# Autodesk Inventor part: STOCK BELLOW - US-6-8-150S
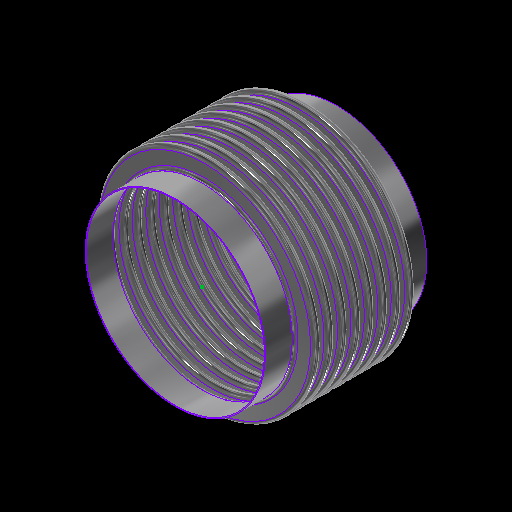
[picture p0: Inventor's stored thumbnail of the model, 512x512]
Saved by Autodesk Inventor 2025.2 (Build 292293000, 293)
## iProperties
Category: 20 GA (0.036 THICK)
RuleStatus: InUse
Created: 2024-01
Part Number: STOCK BELLOW - US-6-8-150S
Project: =STOCK BELLOWS: <Stock Number><SFILL>
Material: ASTM A240-304
Description: =STOCK BELLOWS: <Stock Number>, <SID_> I.D., <SOD_> O.D., <SPLY_> PLY, <Category>, <SNET_CONS> CONS.<PITCH_><STANGENT_> TANGENT<SFILL>
Document SubType Name: Sheet Metal
Designer: GS
Stock Number: U.S-6-8-150S
Surface Area: 4667.05 cm^2
Volume: 212.044 cm^3
Sheet Metal Rule: Default
Appearance: STAINLESS STEEL
Mass: 1708.5 g
Density: 8.05729 g/cm^3
THK: 0.036
ID: 3.500
OD: 4.250
CONS_: 2
PITCH: 0.500
TANGENT: 0.500
BELLOWS_UPSET: 0.000
d79: 1.000
d82: 1.000
d83: 26.000
d84: 24.000
d174: 8
d214: 8
STHK_: 0.036
SID_: 6.625
SOD_: 8.125
SPITCH_: 0.500
STANGENT__: 1.000
SBELLOWS_UPSET_: 0.000
SDIFF_TAN: 1.000
d252: 2
d275: 2
d287: 0.050
d289: 0.500
d290: 0.000
SOD_NECK: 6 11/16
PLY: 1
PSET: 4.178
PBAR: 1.035
COUNTER: 1.500
NET_TUBE: 3.071
CONS: 2
S_CONS: 0
NET_CONS: 2
ID_M: 88.90 mm
OD_M: 107.95 mm
THK_M: 0.91 mm
ID_U: 3.500 in
OD_U: 4.250 in
THK_U: 0.036 in
TANGENT2: 0.500
TAN_TO_TAN: 1.000 in
d80: 2.571
d81: 10
SID: 2.375
SCONS_: 8
SPITCH: 0.250
STANGENT_: 1.000
SBELLOWS_UPSET: 0.000
SNET_CONS: 8
SS_CONS: 0
SCONS: 8
d190: 8
d191: 1
d192: 1
d193: 8
d194: 0
SIZE: 6.00
PRESSURE: 150
d230: 8
STANGENT: 4.000
SPLY_: 1
d233: 8
d234: 0
d263: 2
d265: 1
d268: 2
d269: 0
d286: 2
d288: 1
d291: 2
d292: 0
SREROLL: 0.750
BLETP: 0.000 ul
PRES_Copy: 85
MATTABLE: 20 GA (0.036 THICK)
PART_NUMBER: U.S-6-8-150S
PITCH_: =, <SPITCH_> PITCH,
CFILL: .
SFILL: .
MESH: ,
COMP: 0.83
EXT: 0.42
LAT: 0.15
ANG: 573
ASR: 1823
LSR: 8364
ANSR: 195
PRES: 150
COMPM: 8.3
EXTM: 4.15
LATM: 1.50
ASRM: 319.262
PRESM: 10.342
LSRM: 1464.787
ANSRM: 34.15
TEMPMIN: 20
TEMPMAX: 800
TEMPMINM: -7
TEMPMAXM: 427
WEIGHTM: 1.709
WEIGHT: 3.767
Author: GS
Keywords: 20 GA (0.036 THICK)
Comments: =STOCK BELLOW - <STOCK NUMBER>
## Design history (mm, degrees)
sketch "Sketch2"
  geometry: L1 (0, -177.245)-(0, 562.856) reference; L2 (45.364, 0)-(44.45, 0); L3 (48.082, -2.718)-(50.343, -2.718); L4 (48.082, -3.632)-(50.343, -3.632); L5 (50.343, -9.982)-(48.082, -9.982); L6 (50.343, -9.068)-(48.082, -9.068); L7 (45.364, -12.7)-(44.45, -12.7); L8 (48.082, 0)-(48.082, -12.7); L9 (50.343, -6.35)-(53.975, -6.35); L10 (44.45, 0)-(44.45, -12.7); L11 (20.376, 102.841)-(20.376, 101.926); L12 (58.262, 457.127)-(58.262, 349.177); L13 (58.262, 444.427)-(58.262, 336.477); L14 (93.133, -58.817)-(93.133, -71.517); L15 (118.746, -66.401)-(118.746, -66.401); L16 (50.343, -9.068)-(50.343, -9.982); L17 (48.082, -9.068)-(48.082, -9.982); L18 (48.082, -9.525)-(50.343, -9.525); L19 (53.975, 0)-(53.975, -12.7); L20 (-50.343, -9.068)-(-50.343, -9.982); L21 (-50.343, -2.718)-(-48.082, -2.718); L22 (-50.343, -3.632)-(-48.082, -3.632); L23 (-48.082, -9.068)-(-50.343, -9.068); L24 (-50.343, -9.525)-(-48.082, -9.525); L25 (-48.082, -9.982)-(-50.343, -9.982); L26 (-48.082, -9.068)-(-48.082, -9.982); L27 (-44.45, 0.653)-(-44.45, -12.047); L28 (-48.082, -6.35)-(-44.45, -6.35); L29 (-50.343, 0.653)-(-50.343, -12.7); L30 (-53.061, 0)-(-53.975, 0); L31 (-53.975, 0)-(-53.975, -12.7); L32 (-53.061, -12.7)-(-53.975, -12.7); A1 r 2.718 centre (48.082, 0) between (45.364, 0) and (48.082, -2.718); A2 r 3.632 centre (48.082, 0) between (44.45, 0) and (48.082, -3.632); A3 r 3.632 centre (50.343, -6.35) between (50.343, -9.982) and (50.343, -2.718); A4 r 2.718 centre (50.343, -6.35) between (50.343, -9.068) and (50.343, -3.632); A5 r 2.718 centre (48.082, -12.7) between (48.082, -9.982) and (45.364, -12.7); A6 r 3.632 centre (48.082, -12.7) between (48.082, -9.068) and (44.45, -12.7); A7 r 3.175 centre (50.343, -6.35) between (50.343, -9.525) and (53.518, -6.35); A8 r 3.175 centre (48.082, -12.7) between (48.082, -9.525) and (44.907, -12.7); A9 r 2.718 centre (-50.343, -12.7) between (-50.343, -9.982) and (-53.061, -12.7); A10 r 2.718 centre (-48.082, -6.35) between (-48.082, -9.068) and (-48.082, -3.632); A11 r 3.175 centre (-48.082, -6.35) between (-48.082, -9.525) and (-44.907, -6.35); A12 r 3.632 centre (-48.082, -6.35) between (-48.082, -9.982) and (-48.082, -2.718); A13 r 3.175 centre (-50.343, -12.7) between (-50.343, -9.525) and (-53.518, -12.7); A14 r 3.632 centre (-50.343, -12.7) between (-50.343, -9.068) and (-53.975, -12.7); A15 r 2.718 centre (-50.343, 0) between (-53.061, 0) and (-50.343, -2.718); A16 r 3.632 centre (-50.343, 0) between (-53.975, 0) and (-50.343, -3.632); 10 further points
  constraints: 62 end point, 38 point on circle, 20 tangent, 16 centre point, 12 parallel, 9 midpoint, 7 vertical, 6 coincident, 6 concentric, 6 point on line, 4 equal radius, 4 perpendicular, 3 horizontal, 1 collinear, 1 horizontal alignment, 10 other
  dimensions: "THK" = 0.9144 distance of L11.start L11.end; "ID" = 88.9 distance of L11.end point (20.376, 13.026); "OD" = 107.95 distance of L12.start L12.end; "PITCH" = 12.7 distance of L12.start L13.start; "TANGENT" = 12.7 distance of L14.start L14.end; "BELLOWS_UPSET" = 0 distance of L15.start L15.end; "d43" = 88.9 diameter of L10 L1 (= ID); "d44" = 107.95 diameter of L9.end L1 (= OD); "d45" = 0.9144 distance between parallel lines of L5 L6 (computed from THK, PLY); "d46" = 3.6322 radius of A3 (computed from PITCH, THK, PLY); "UPSET_PITCH" = 12.7 distance of L2.end L7.end (derived); "SIDEWALL_ANGLE" = 360 deg dimension on L3 L9 (derived); "CON_GAP" = 5.4356 distance of point (48.082, -9.068) point (48.082, -3.632) (derived); "TAN1" = 4.98728 dimension on A8 (derived); "TAN2" = 4.98728 dimension on A7 (derived); "LEG1" = 2.2606 distance of L18.start L18.end (derived); "d278" = 0.9144 distance between parallel lines of L25 L23 (derived); "d279" = 3.6322 radius of A12 (derived); "d280" = 12.7 distance of L30.end L31.end (derived); "d281" = 360 deg dimension on L21 L28 (derived); "d282" = 5.4356 distance of point (-50.343, -9.068) point (-50.343, -3.632) (derived); "d283" = 4.98728 dimension on A13 (derived); "d284" = 4.98728 dimension on A11 (derived); "d285" = 2.2606 distance of L24.start L24.end (derived); "d293" = 88.9 diameter of L27 L1 (derived); "d294" = 107.95 diameter of L31 L1 (derived)
  node "Sketch Rectangular Pattern1" dims "d31" = 25.4, "ID" = 88.9
  node "Sketch Rectangular Pattern2" dims "d39" = 25.4, "PITCH" = 12.7
revolve "CONS" stored, may be unused: angle "d48" = 90 deg
node "BELLOW MIDPLANE"
pattern_linear "Rectangular Pattern2" dims "d52" = 12.7 (= UPSET_PITCH)
sketch "Sketch5"
  geometry: C1 r 45.364 at (0, 0) reference; C2 r 44.45 at (0, 0) reference
extrude "TANGENT" new body sketch "Sketch5" distance "d53" = 12.7 (= TANGENT); taper "d54" = 0 deg
revolve "SAMETAN" stored, may be unused: angle "d65" = 90 deg
revolve "DIFFTAN" stored, may be unused: angle "d70" = 90 deg
sketch "Sketch9"
  geometry: L1 (53.319, 0)-(-53.319, 0) reference; L2 (0, -17.78)-(0, 17.78) reference; L3 (38.085, 0)-(-38.085, 0); L4 (38.085, -11.906)-(38.085, 11.906); L5 (25.385, -11.906)-(25.385, 11.906); L6 (13.15, 11.906)-(13.15, -11.906); L7 (-25.385, -11.906)-(-25.385, 11.906); L8 (-38.085, -11.906)-(-38.085, 11.906); L9 (37.291, -11.906)-(37.291, 11.906); L10 (38.085, -11.906)-(37.291, -11.906); L11 (38.085, 11.906)-(37.291, 11.906); L12 (13.546, 11.906)-(12.753, 11.906); L13 (12.753, 11.906)-(12.753, -11.906); L14 (12.753, -11.906)-(13.546, -11.906); L15 (13.546, -11.906)-(13.546, 11.906); L16 (-13.546, 11.906)-(-13.546, -11.906); L17 (-13.15, 11.906)-(-13.15, -11.906); L18 (-13.546, -11.906)-(-12.753, -11.906); L19 (-12.753, -11.906)-(-12.753, 11.906); L20 (-12.753, 11.906)-(-13.546, 11.906); L21 (-38.085, -11.906)-(-37.291, -11.906); L22 (-37.291, -11.906)-(-37.291, 11.906); L23 (-37.291, 11.906)-(-38.085, 11.906); L24 (-38.085, 11.906)-(-38.085, -11.906); L25 (38.085, -0.397)-(-38.085, -0.397); L26 (-38.085, -0.397)-(-38.085, 0.397); L27 (-38.085, 0.397)-(38.085, 0.397); L28 (38.085, 0.397)-(38.085, -0.397); L29 (-38.085, 11.906)-(38.085, 11.906); L30 (38.085, 11.906)-(38.085, 12.7); L31 (38.085, 12.7)-(-38.085, 12.7); L32 (-38.085, 12.7)-(-38.085, 11.906); L33 (38.085, -11.906)-(-38.085, -11.906); L34 (-38.085, -11.906)-(-38.085, -12.7); L35 (-38.085, -12.7)-(38.085, -12.7); L36 (38.085, -12.7)-(38.085, -11.906); 30 further points
  constraints: 68 end point, 13 midpoint, 13 parallel, 8 horizontal, 7 perpendicular, 6 equal length, 3 point on line, 2 vertical, 14 other
  dimensions: "d115" = 23.8125 distance of L4.start L4.end (derived); "d116" = 12.7 distance between parallel lines of L4 L5 (derived); "d117" = 12.23516 distance between parallel lines of L5 L6 (derived); "d125" = 38.53427 distance between parallel lines of L7 L6 (derived); "d127" = 12.7 distance between parallel lines of L8 L7 (derived); "d128" = 24.93516 distance between parallel lines of L6 L4 (derived); "d130" = 76.16943 distance between parallel lines of L8 L4 (derived); "RULER_THK" = 0.79375 distance between parallel lines of L4 L9; "d135" = 0.79375 distance of L13.end L14.end (derived); "d138" = 26.29911 distance of L13.end L16.end (derived); "d143" = 0.79375 distance of L22.end L8.end (derived); "d144" = 0.79375 distance between parallel lines of L27 L25 (derived)
extrude "RULER" join sketch "Sketch9" distance "d149" = 0.79375 (derived); taper "d150" = 0 deg
extrude "BARS" join sketch "Sketch9" distance "d151" = 0.79375 (derived); taper "d152" = 0 deg
pattern_linear "Rectangular Pattern4" dims "d155" = 26.29911 (derived)
sketch "Sketch13"
  geometry: L1 (93.149, -52.467)-(93.149, -77.867); L2 (85.052, 0)-(84.138, 0); L3 (85.052, -12.7)-(84.138, -12.7); L4 (99.555, -9.982)-(87.77, -9.982); L5 (99.555, -9.068)-(87.77, -9.068); L6 (99.555, -6.35)-(103.188, -6.35); L7 (87.77, -2.718)-(99.555, -2.718); L8 (87.77, 0)-(87.77, -12.7); L9 (84.138, 0)-(84.138, -12.7); L10 (58.254, -290.056)-(58.254, -496.431); L11 (58.254, -302.756)-(58.254, -509.131); L12 (58.254, -328.156)-(58.254, -534.531); L13 (58.254, -340.856)-(58.254, -547.231); L14 (58.254, -353.556)-(58.254, -559.931); L15 (58.254, -366.256)-(58.254, -572.631); L16 (58.254, -378.956)-(58.254, -585.331); L17 (58.254, -315.456)-(58.254, -521.831); L18 (20.376, 102.841)-(20.376, 101.926); L19 (87.77, -3.632)-(99.555, -3.632); L20 (0, -722.965)-(0, 240.475) reference; L21 (-23.752, 0)-(142.514, 0) reference; A1 r 2.718 centre (87.77, 0) between (85.052, 0) and (87.77, -2.718); A2 r 2.718 centre (87.77, -12.7) between (87.77, -9.982) and (85.052, -12.7); A3 r 3.632 centre (87.77, -12.7) between (87.77, -9.068) and (84.138, -12.7); A4 r 2.718 centre (99.555, -6.35) between (99.555, -9.068) and (99.555, -3.632); A5 r 3.632 centre (99.555, -6.35) between (99.555, -9.982) and (99.555, -2.718); A6 r 3.632 centre (87.77, 0) between (84.138, 0) and (87.77, -3.632); 6 further points; 1 other entity
  constraints: 38 end point, 15 point on circle, 9 tangent, 6 centre point, 6 parallel, 5 vertical alignment, 4 point on line, 4 vertical, 3 coincident, 3 concentric, 2 collinear, 2 equal radius, 1 horizontal, 1 perpendicular, 23 other
  dimensions: "SBELLOWS_UPSET_" = 0 distance of point (118.762, -66.401) point (118.762, -66.401); "STOTAL_THK_BELLOW__" = 0.9144 distance between parallel lines of L4 L5 (derived); "d224" = 3.6322 radius of A5 (derived); "d225" = 12.7 distance of L2.end L3.end (derived); "SSIDEWALL_ANGLE_" = 0 deg angle of L7 L6 (derived); "SSCON_GAP_" = 5.4356 distance of point (87.77, -9.068) point (87.77, -3.632) (derived); "d235" = 168.275 diameter of L9 L20 (derived); "d236" = 206.375 diameter of L6.end L20 (derived)
  node "Sketch Rectangular Pattern4" dims "d228" = 25.4
  node "Sketch Rectangular Pattern5" dims "d229" = 25.4
revolve "SBELLOW" stored, may be unused: angle "d197" = 90 deg
pattern_linear "Rectangular Pattern5" dims "d204" = 12.7 (derived)
revolve "STANGENT" stored, may be unused: angle "d240" = 90 deg
revolve "SSAMETAN" stored, may be unused: angle "d241" = 90 deg
revolve "SDIFFTAN" stored, may be unused: angle "d246" = 90 deg
revolve "INVCON" stored, may be unused: angle "d295" = 90 deg
pattern_linear "Rectangular Pattern6" dims "d298" = 12.7 (derived)
revolve "INVTANGENT" stored, may be unused: angle "d302" = 90 deg
revolve "INVSAMETAN" stored, may be unused: angle "d307" = 90 deg
revolve "INVDIFFTAN" stored, may be unused: angle "d312" = 90 deg
sketch "ID BELLOW MOUNT CALC"
  geometry: L1 (44.45, 0)-(38.1, 0); L2 (38.1, 0)-(38.1, 12.7); L3 (38.1, 12.7)-(44.45, 12.7); L4 (44.45, 12.7)-(44.45, 0); L5 (36.513, 12.7)-(35.598, 12.7); L6 (35.598, 12.7)-(35.598, 0); L7 (35.598, 0)-(36.513, 0); L8 (36.513, 0)-(36.513, 12.7); L9 (0, -2.54)-(0, 15.24) reference; L10 (-8.89, 0)-(53.34, 0) reference; 1 further point
  constraints: 16 end point, 5 parallel, 2 collinear, 2 horizontal, 2 perpendicular
  dimensions: "d314" = 12.7 distance of L5.end L6.end (derived); "d315" = 0.9144 distance of L5.start L5.end (derived); "IG" = 1.5875 distance between parallel lines of L2 L8; "PIPE_OD" = 88.9 diameter of L4 L9; "PIPE_WALL" = 6.35 distance of L2.end L3.end; "ID_MT_BELLOW" = 71.1962 diameter of L6 L9 (derived)
revolve "CFILL" stored, may be unused: angle "d320" = 90 deg
pattern_linear "Rectangular Pattern7" dims "d323" = 12.7 (derived)
revolve "SFILL" stored, may be unused: angle "d324" = 90 deg
pattern_linear "Rectangular Pattern8" dims "d327" = 12.7 (derived)
node "STOCK BELLOW MIDPLANE"
node "BELLOW"
sketch "Sketch6"
  geometry: L1 (-12.7, 45.364)-(0, 45.364); L2 (0, 45.364)-(0, 44.45); L3 (0, 44.45)-(-12.7, 44.45); L4 (-12.7, 44.45)-(-12.7, 45.364); L5 (10.16, 0)-(-60.96, 0) reference; L6 (-38.1, -89.422)-(-38.1, 153.44) reference; 1 further point
  constraints: 8 end point, 2 parallel, 1 horizontal, 1 perpendicular
  dimensions: "d61" = 12.7 distance of L2.end L3.end (derived); "d62" = 0.9144 distance of L1.end L2.end (derived); "d63" = 88.9 diameter of L3 L5 (derived); "d64" = 25.4 distance between parallel lines of L4 L6 (derived)
sketch "Sketch12"
  geometry: 1 further point
sketch "Sketch14"
  geometry: L1 (-25.4, 85.052)-(0, 85.052); L2 (0, 85.052)-(0, 84.138); L3 (0, 84.138)-(-25.4, 84.138); L4 (-25.4, 84.138)-(-25.4, 85.052); L5 (5.08, 0)-(-30.48, 0) reference; L6 (0, -17.01)-(0, 102.062) reference; 1 further point
  constraints: 8 end point, 2 parallel, 1 collinear, 1 horizontal, 1 perpendicular
  dimensions: "d237" = 0.9144 distance of L3.end L1.start (derived); "d238" = 168.275 diameter of L3 L5 (derived); "d239" = 25.4 distance of L1.start L1.end (derived); "SOD_NECK" = 170.1038 diameter of L1 L5 (derived)
sketch "Sketch15"
  geometry: L1 (-17.01, 0)-(102.062, 0) reference; L2 (84.138, -101.6)-(85.052, -101.6); L3 (85.052, -101.6)-(85.052, -127); L4 (85.052, -127)-(84.138, -127); L5 (84.138, -127)-(84.138, -101.6); L6 (0, -154.94)-(0, 40.64) reference; 1 further point
  constraints: 8 end point, 2 parallel, 1 horizontal, 1 perpendicular
  dimensions: "d205" = 25.4 distance of L4.end L2.start (derived); "d206" = 0.9144 distance of L3.end L4.end (derived); "d207" = 168.275 diameter of L5 L6 (derived); "d208" = 101.6 distance between parallel lines of L1 L2 (derived)
node "TANGENT_"
node "SAME_TAN"
sketch "Sketch8"
  geometry: L1 (45.364, -25.4)-(44.45, -25.4); L2 (44.45, -25.4)-(44.45, -38.1); L3 (44.45, -38.1)-(45.364, -38.1); L4 (45.364, -38.1)-(45.364, -25.4); L5 (0, -48.26)-(0, 22.86) reference; L6 (-89.422, 0)-(153.44, 0) reference; 1 further point
  constraints: 8 end point, 2 parallel, 1 horizontal, 1 perpendicular
  dimensions: "d66" = 88.9 diameter of L2 L5 (derived); "TOTAL_THK_BELLOW" = 0.9144 distance of L2.end L3.end (derived); "d68" = 25.4 distance between parallel lines of L1 L6 (derived); "d69" = 12.7 distance of L1.end L2.end (derived)
node "DIFF_TAN"
node "Sketch Rectangular Pattern3" dims "d138" = 26.29911 (derived), "d141" = 25.4
node "SBELLOW_"
node "STANGENT_"
node "SSAME_TAN"
sketch "Sketch16"
  geometry: L1 (85.052, -101.6)-(84.138, -101.6); L2 (84.138, -101.6)-(84.138, -127); L3 (84.138, -127)-(85.052, -127); L4 (85.052, -127)-(85.052, -101.6); L5 (0, -154.94)-(0, 40.64) reference; L6 (-17.01, 0)-(102.062, 0) reference; 1 further point
  constraints: 8 end point, 2 parallel, 1 horizontal, 1 perpendicular
  dimensions: "SDIFF_TAN" = 25.4 distance of L3.end L1.start; "d243" = 0.9144 distance of L2.end L3.end (derived); "d244" = 101.6 distance between parallel lines of L1 L6 (derived); "d245" = 168.275 diameter of L2 L5 (derived)
node "SDIFF_TAN"
body "Solid15"
sketch "Sketch17"
  geometry: L1 (53.975, 12.7)-(53.061, 12.7); L2 (53.061, 12.7)-(53.061, 0); L3 (53.061, 0)-(53.975, 0); L4 (53.975, 0)-(53.975, 12.7); L5 (0, -2.54)-(0, 15.24) reference; L6 (-10.795, 0)-(64.77, 0) reference; 2 further points
  constraints: 8 end point, 2 parallel, 1 horizontal, 1 midpoint, 1 perpendicular, 1 point on line
  dimensions: "INVTANGENT" = 12.7 distance of L3.end L1.start (derived); "d300" = 0.9144 distance of L1.start L1.end (derived); "d301" = 107.95 diameter of L4 L5 (derived)
body "Solid16"
sketch "Sketch18"
  geometry: L1 (53.975, -25.4)-(53.061, -25.4); L2 (53.061, -25.4)-(53.061, -38.1); L3 (53.061, -38.1)-(53.975, -38.1); L4 (53.975, -38.1)-(53.975, -25.4); L5 (-10.795, 0)-(64.77, 0) reference; L6 (0, -48.26)-(0, 22.86) reference; 1 further point
  constraints: 8 end point, 2 parallel, 1 horizontal, 1 perpendicular
  dimensions: "d303" = 25.4 distance between parallel lines of L1 L5 (derived); "d304" = 12.7 distance of L3.end L1.start (derived); "d305" = 0.9144 distance of L2.end L3.end (derived); "d306" = 107.95 diameter of L4 L6 (derived)
body "Solid17"
sketch "Sketch19"
  geometry: L1 (53.975, -25.4)-(53.061, -25.4); L2 (53.061, -25.4)-(53.061, -38.1); L3 (53.061, -38.1)-(53.975, -38.1); L4 (53.975, -38.1)-(53.975, -25.4); L5 (0, -48.26)-(0, 22.86) reference; L6 (-10.795, 0)-(64.77, 0) reference; 1 further point
  constraints: 8 end point, 2 parallel, 1 horizontal, 1 perpendicular
  dimensions: "d308" = 12.7 distance of L1.end L2.end (derived); "d309" = 107.95 diameter of L4 L5 (derived); "d310" = 0.9144 distance of L2.end L3.end (derived); "d311" = 25.4 distance between parallel lines of L1 L6 (derived)
body "Solid18"
body "Solid19"
body "Solid20"
other parameters: "BMPL" = -50.8, "PSET" = 106.1212 (computed from OD, THK, PLY) [user parameter], "PBAR" = 26.29911 (= 0.570796 x PITCH + OD - ID) [user parameter; used in 1 equation term], "COUNTER" = 15 [user parameter], "NET_TUBE" = 77.99823 (computed from CONS_, PBAR, TANGENT) [user parameter], "S_CONS" = 0 [user parameter; used in 1 equation term], "ID_M" = 88.9 (= ID) [user parameter], "OD_M" = 107.95 (= OD) [user parameter], "THK_M" = 0.9144 (= THK) [user parameter], "ID_U" = 88.9 (= ID) [user parameter], "OD_U" = 107.95 (= OD) [user parameter], "THK_U" = 0.9144 (= THK) [user parameter], "D_UNITS" = 0 [user parameter], "TANGENT2" = 12.7 [user parameter], "TAN_TO_TAN" = 25.4 [user parameter], "OD_NECK" = 90.7288 [user parameter], "d79" = 25.4, "d80" = 65.29823 [user parameter], "d82" = 25.4, "d83" = 660.4, "d84" = 609.6, "sa_0" = 4, "FRAME_THK" = 0.79375 [user parameter], "CON_FLAT" = 12.23516 [user parameter], "SID" = 60.325 [user parameter], "SPITCH" = 6.35 [user parameter], "STANGENT_" = 25.4 [user parameter], "SBELLOWS_UPSET" = 0 [user parameter], "SS_CONS" = 0 [user parameter], "STAN_TO_TAN_" = 101.6 [user parameter], "d100" = 0.9144 [user parameter], "d191" = 25.4 [user parameter], "d194" = 0 [user parameter], "STANGENT" = 101.6 [user parameter], "d234" = 0 [user parameter], "SUPSET_PITCH_" = 12.7 [user parameter], "d269" = 0 [user parameter], "d287" = 1.27, "d289" = 12.7, "d290" = 0, "d292" = 0 [user parameter], "Thickness" = 3.048 (derived), "KFactor" = 4.4, "BendRadius" = 3.048 (derived), "BendReliefWidth" = 3.048 (derived), "BendReliefDepth" = 1.524 (derived), "CornerReliefSize" = 12.192 (derived), "SeamGap" = 0.00508, "MinimumRemnant" = 6.096 (derived), "TransitionRadius" = 3.048 (derived), "JacobiRadiusSize" = 3.048 (derived), "GapSize" = 3.048 (derived), "SREROLL" = 19.05 [user parameter], "CUR_STK_PITCH" = 12.7 [user parameter], "d328" = -50.8 (derived), "ASR" = 18230 [user parameter], "LSR" = 83640 [user parameter], "BLETP" = 0 [user parameter], "ASRM" = 3192.6199 [user parameter], "PRESM" = 103.41975 [user parameter], "LSRM" = 14647.8732 [user parameter], "ANSRM" = 341.5035 [user parameter], "TEMPMIN" = 2664.83333 [user parameter], "TEMPMAX" = 6998.16667 [user parameter], "TEMPMINM" = 2664.83333 [user parameter], "TEMPMAXM" = 6998.16667 [user parameter], "WEIGHT" = 17.08503 [user parameter], "WEIGHTM" = 0.01709 [user parameter]
